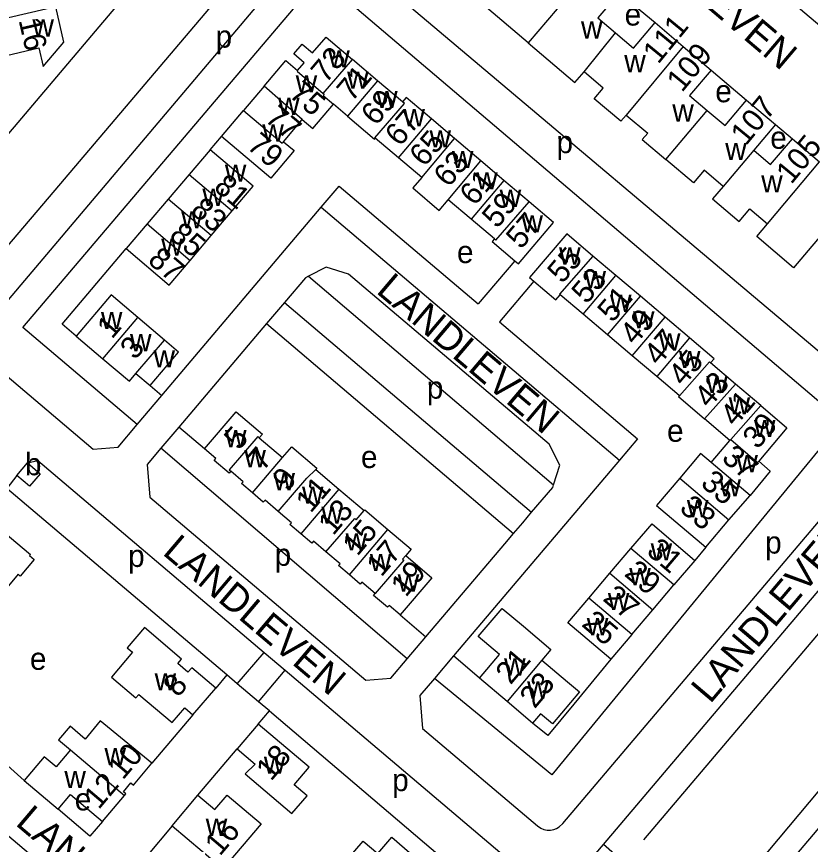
# Model space of a CAD drawing. Extents: x 155696 to 157795, y 382328 to 384028.
# Drawn here: x 156838 to 156980.5, y 382424.3 to 382573 of the extents above; entities that cross this region are included whole.
import ezdxf

# ---------------------------------------------------------------- set-up
doc = ezdxf.new("R2010")
doc.units = 0
for name, color, linetype in [('BLT_Basislijn', 7, 'Continuous'), ('BLT_Bebouwing', 7, 'Continuous'), ('BLT_Centroide', 7, 'Continuous'), ('BLT_Gemeentegrens', 7, 'Continuous'), ('BLT_Huisnummer', 7, 'Continuous'), ('BLT_Huisnummer_ tussenligend', 7, 'Continuous'), ('BLT_Onderverdeling_panden', 7, 'Continuous'), ('BLT_Straatnaam', 7, 'Continuous')]:
    doc.layers.add(name, color=color, linetype=linetype)

msp = doc.modelspace()

# ---------------------------------------------------------------- linework, layer by layer
at = {"layer": 'BLT_Basislijn'}
for p, q in [((156997.06, 382500.08), (156894.28, 382586.82)), ((156834.46, 382519.74), (156886.08, 382580.75)), ((156986.19, 382500.27), (156892.45, 382580.02)), ((156946.2, 382577.33), (156952.62, 382571.89)), ((156856.41, 382575.46), (156785.51, 382491.83)), ((156962.68, 382563.37), (156969.05, 382557.96)), ((156974.2, 382553.6), (156977.27, 382551)), ((156872.74, 382549.06), (156874.76, 382551.45)), ((156927.42, 382529.15), (156920.86, 382521.41)), ((156890.37, 382526.35), (156934.37, 382488.9)), ((156930.85, 382525.47), (156924.67, 382518.17)), ((156886.09, 382521.66), (156930.44, 382483.98)), ((157054.68, 382520.73), (156894.99, 382330.24)), ((156882.85, 382517.84), (156867.11, 382499.28)), ((156882.85, 382517.84), (156927.21, 382480.16)), ((156861.95, 382506.75), (156864.06, 382504.96)), ((156867.11, 382499.28), (156863.88, 382495.46)), ((156871.72, 382495.34), (156867.11, 382499.28)), ((156851.73, 382495.32), (156856.2, 382495.69)), ((156863.88, 382495.46), (156861.43, 382492.57)), ((156908.11, 382457.64), (156863.88, 382495.46)), ((156861.43, 382492.57), (156861.91, 382486.69)), ((156838.01, 382490.58), (156836.21, 382488.23)), ((156875.7, 382454.77), (156836.21, 382488.23)), ((156950.61, 382425.19), (157004.61, 382488.89)), ((156925.62, 382478.29), (156927.21, 382480.16)), ((156911.47, 382461.6), (156925.62, 382478.29)), ((156961.72, 382477.72), (156959.75, 382475.33)), ((156906.87, 382465.54), (156911.47, 382461.6)), ((156908.11, 382457.64), (156911.47, 382461.6)), ((156877.59, 382453.17), (156882.4, 382458.83)), ((156905.18, 382454.18), (156908.11, 382457.64)), ((156921.08, 382454.21), (156916.44, 382458.18)), ((156881.41, 382449.94), (156886.21, 382455.6)), ((156900.7, 382453.81), (156905.18, 382454.18)), ((156821.86, 382451.43), (156839.32, 382435.82)), ((156910.4, 382451.06), (156910.88, 382445.17)), ((156883.36, 382448.3), (156922.98, 382414.65)), ((156869.65, 382447.63), (156862.26, 382438.91)), ((156870.54, 382433.19), (156877.58, 382441.51)), ((156851.14, 382425.81), (156845.43, 382430.65)), ((156853.41, 382428.48), (156851.14, 382425.81))]:
    msp.add_line(p, q, dxfattribs=at)
for points in [[(156843.9, 382540.6), (156883.65, 382587.5)], [(156859.64, 382499.75), (156839.11, 382517.17), (156892.45, 382580.02)], [(156892.69, 382538.73), (156895.92, 382542.54), (156920.86, 382521.41)], [(156824.76, 382518.18), (156843.9, 382540.6)], [(156864.06, 382504.96), (156892.69, 382538.73)], [(156892.69, 382538.73), (156946.24, 382493.33)], [(156848.7, 382515.6), (156846.16, 382517.75), (156857.67, 382531.31)], [(156934.37, 382488.9), (156935.51, 382492.45), (156933.59, 382496.19), (156897.58, 382526.72), (156893.58, 382528), (156890.37, 382526.35)], [(156890.37, 382526.35), (156889.83, 382526.08), (156886.09, 382521.66)], [(156886.09, 382521.66), (156882.85, 382517.84)], [(156824.76, 382518.18), (156851.73, 382495.32)], [(156924.67, 382518.17), (156949.47, 382497.15), (156946.24, 382493.33)], [(156859.64, 382499.75), (156864.06, 382504.96)], [(156986.19, 382500.27), (156934.07, 382436.84), (156913.01, 382454.14)], [(156856.2, 382495.69), (156859.64, 382499.75)], [(156943.34, 382424.34), (157004.11, 382496.03)], [(156910.88, 382445.17), (156931.52, 382427.68), (156932.08, 382427.28), (156932.61, 382427.04), (156933.21, 382426.9), (156933.85, 382426.89), (156934.44, 382427), (156934.92, 382427.19), (156935.4, 382427.49), (156936.02, 382428.08), (156992.6, 382494.82)], [(156839.93, 382492.83), (156841.8, 382493.25), (156882.4, 382458.83)], [(156946.24, 382493.33), (156916.44, 382458.18)], [(156930.44, 382483.98), (156934.23, 382488.44), (156934.37, 382488.9)], [(156861.91, 382486.69), (156900.7, 382453.81)], [(156928.85, 382482.1), (156930.44, 382483.98)], [(156927.21, 382480.16), (156928.85, 382482.1)], [(156882.4, 382458.83), (156886.21, 382455.6)], [(156916.44, 382458.18), (156913.01, 382454.14)], [(156944.64, 382457.59), (156938.01, 382449.51)], [(156886.21, 382455.6), (156924.76, 382422.93)], [(156875.7, 382454.77), (156873.72, 382452.42)], [(156877.59, 382453.17), (156875.7, 382454.77)], [(156913.01, 382454.14), (156910.4, 382451.06)], [(156881.41, 382449.94), (156877.59, 382453.17)], [(156889.25, 382381.11), (156808.2, 382449.76)], [(156883.36, 382448.3), (156881.41, 382449.94)], [(156881.37, 382445.94), (156883.36, 382448.3)], [(156938.01, 382449.51), (156933.38, 382443.88), (156930.62, 382446.14)], [(156932.77, 382404.72), (156946.82, 382421.3), (156943.34, 382424.34)], [(156934.87, 382414.35), (156943.34, 382424.34)]]:
    msp.add_lwpolyline(points, dxfattribs=at)
at = {"layer": 'BLT_Bebouwing'}
for p, q in [((156929.84, 382568.25), (156921.59, 382575.24)), ((156842.76, 382564), (156846.49, 382568.4)), ((156902.78, 382561.45), (156898.3, 382565.25)), ((156907.26, 382557.65), (156902.78, 382561.45)), ((156882.41, 382560.47), (156878.72, 382556.13)), ((156897.39, 382555.09), (156894.88, 382557.23)), ((156885.89, 382550.51), (156889.27, 382554.5)), ((156916.59, 382551.08), (156912.44, 382554.6)), ((156906.56, 382547.63), (156902.38, 382551.16)), ((156921.31, 382547.07), (156916.59, 382551.08)), ((156910.74, 382544.11), (156906.56, 382547.63)), ((156925.46, 382543.55), (156921.31, 382547.07)), ((156868.98, 382544.63), (156865.21, 382540.19)), ((156929.99, 382539.71), (156925.46, 382543.55)), ((156865.21, 382540.19), (156861.44, 382535.75)), ((156919.61, 382536.58), (156915.45, 382540.09)), ((156872.91, 382533.65), (156876.67, 382538.09)), ((156923.77, 382533.05), (156919.61, 382536.58)), ((156869.14, 382529.21), (156872.91, 382533.65)), ((156945.56, 382526.5), (156941.46, 382529.98)), ((156949.97, 382522.76), (156945.56, 382526.5)), ((156939.67, 382519.56), (156935.57, 382523.04)), ((156954.39, 382519.02), (156949.97, 382522.76)), ((156944.09, 382515.82), (156939.67, 382519.56)), ((156864.53, 382514.88), (156859.77, 382518.92)), ((156958.8, 382515.28), (156954.39, 382519.02)), ((156948.5, 382512.08), (156944.09, 382515.82)), ((156952.91, 382508.34), (156948.5, 382512.08)), ((156967.03, 382507), (156962.55, 382510.79)), ((156956.94, 382504.92), (156952.91, 382508.34)), ((156971.57, 382503.15), (156967.03, 382507)), ((156966.04, 382496.88), (156961.51, 382500.74)), ((156881.54, 382497.37), (156885.72, 382493.83)), ((156962.69, 382492.92), (156966.04, 382496.88)), ((156965.86, 382482.61), (156969.67, 382486.99)), ((156944.5, 382473.02), (156948.28, 382477.47)), ((156940.74, 382468.58), (156944.5, 382473.02)), ((156952.21, 382466.47), (156956, 382470.93)), ((156948.44, 382462.04), (156952.21, 382466.47))]:
    msp.add_line(p, q, dxfattribs=at)
for points in [[(156946.2, 382577.33), (156942.31, 382572.75), (156945.52, 382570.03)], [(156846.49, 382568.4), (156845.03, 382574.73), (156834.68, 382572.34)], [(156977.95, 382574.98), (156982.98, 382570.71)], [(156945.52, 382570.03), (156948.74, 382567.3), (156952.62, 382571.89)], [(156952.62, 382571.89), (156957.65, 382567.63)], [(156888.44, 382563.3), (156889.61, 382564.69), (156887.75, 382566.27), (156889.23, 382568.02), (156891.09, 382566.44), (156893.53, 382569.3), (156898.3, 382565.25)], [(156836.14, 382566.01), (156841.99, 382567.36), (156842.76, 382564)], [(156929.84, 382568.25), (156938.23, 382561.15), (156939.86, 382563.05)], [(156957.65, 382567.63), (156962.68, 382563.37)], [(156882.41, 382560.47), (156886.33, 382565.09), (156888.44, 382563.3)], [(156947.42, 382555.29), (156946.46, 382554.18), (156941.67, 382558.23), (156943.29, 382560.14), (156939.86, 382563.05)], [(156962.68, 382563.37), (156958.8, 382558.79), (156961.98, 382556.09)], [(156912.44, 382554.6), (156907.92, 382558.42), (156907.26, 382557.65)], [(156889.27, 382554.5), (156891.17, 382552.85), (156894.88, 382557.23)], [(156961.98, 382556.09), (156965.17, 382553.39), (156969.05, 382557.96)], [(156969.05, 382557.96), (156974.2, 382553.6)], [(156874.76, 382551.45), (156878.72, 382556.13)], [(156897.39, 382555.09), (156902.22, 382550.99), (156902.38, 382551.16)], [(156947.42, 382555.29), (156951.28, 382552.05), (156950.31, 382550.93), (156954.56, 382547.32)], [(156974.2, 382553.6), (156970.32, 382549.01)], [(156885.89, 382550.51), (156887.8, 382548.9), (156883.61, 382543.94), (156874.76, 382551.45)], [(156970.32, 382549.01), (156973.36, 382546.44), (156977.27, 382551)], [(156977.27, 382551), (156982.12, 382546.87)], [(156872.74, 382549.06), (156868.98, 382544.63)], [(156876.67, 382538.09), (156880.44, 382542.53), (156872.74, 382549.06)], [(156964.82, 382542.47), (156961.43, 382545.4), (156959.5, 382543.13), (156954.56, 382547.32)], [(156991.99, 382545.05), (156977.45, 382527.89), (156970.86, 382533.51), (156972.79, 382535.79)], [(156910.74, 382544.11), (156909.11, 382542.21), (156913.83, 382538.17), (156915.45, 382540.09)], [(156964.82, 382542.47), (156962.91, 382540.26), (156967.7, 382536.16), (156969.64, 382538.43), (156972.79, 382535.79)], [(156934.36, 382536), (156929.99, 382539.71)], [(156927.42, 382529.15), (156928.09, 382528.59), (156934.36, 382536)], [(156861.44, 382535.75), (156857.67, 382531.31)], [(156923.77, 382533.05), (156923.38, 382532.59), (156927.42, 382529.15)], [(156936.74, 382533.98), (156930.08, 382526.13), (156930.85, 382525.47)], [(156941.46, 382529.98), (156936.74, 382533.98)], [(156857.67, 382531.31), (156865.38, 382524.78), (156869.14, 382529.21)], [(156930.85, 382525.47), (156934.8, 382522.12), (156935.57, 382523.04)], [(156859.77, 382518.92), (156854.97, 382523), (156848.7, 382515.6)], [(156848.7, 382515.6), (156853.44, 382511.53)], [(156962.55, 382510.79), (156963.21, 382511.54), (156958.8, 382515.28)], [(156861.95, 382506.75), (156867.04, 382512.75), (156864.53, 382514.88)], [(156853.44, 382511.53), (156858.23, 382507.52), (156859.41, 382508.9)], [(156859.41, 382508.9), (156861.95, 382506.75)], [(156956.94, 382504.92), (156956.8, 382504.74), (156961.51, 382500.74)], [(156971.57, 382503.15), (156976.29, 382499.15), (156971.21, 382493.15)], [(156871.72, 382495.34), (156877.4, 382502.02), (156882.1, 382498), (156881.54, 382497.37)], [(156885.72, 382493.83), (156887.38, 382495.72), (156891.91, 382491.88), (156891.71, 382491.66)], [(156876.45, 382491.34), (156876.16, 382491), (156873.43, 382493.3), (156873.73, 382493.64), (156871.72, 382495.34)], [(156962.69, 382492.92), (156960.78, 382494.53), (156957.03, 382490.11)], [(156838.01, 382490.58), (156839.93, 382492.83)], [(156839.93, 382492.83), (156842.2, 382490.9), (156840.27, 382488.65), (156838.01, 382490.58)], [(156971.21, 382493.15), (156973.29, 382491.37), (156969.67, 382486.99)], [(156880.34, 382487.47), (156878.37, 382489.13), (156878.66, 382489.47), (156876.45, 382491.34)], [(156891.71, 382491.66), (156895.84, 382488.15)], [(156957.03, 382490.11), (156952.89, 382485.22), (156961.72, 382477.72)], [(156884.94, 382484.14), (156882.58, 382486.14), (156882.27, 382485.82), (156880.34, 382487.47)], [(156895.84, 382488.15), (156900.37, 382484.3)], [(156889.02, 382480.11), (156887.06, 382481.77), (156887.35, 382482.1), (156884.94, 382484.14)], [(156900.37, 382484.3), (156900.48, 382484.43), (156904.65, 382480.89)], [(156961.72, 382477.72), (156965.86, 382482.61)], [(156904.65, 382480.89), (156908.82, 382477.36), (156907.85, 382476.22)], [(156948.28, 382477.47), (156952.07, 382481.93), (156959.75, 382475.33)], [(156830.13, 382480.33), (156833.18, 382477.74), (156835.54, 382480.52), (156840.46, 382476.39), (156840.3, 382476.2), (156841.14, 382475.5), (156838.62, 382472.53), (156838.24, 382472.85), (156834.66, 382468.63)], [(156893.52, 382476.87), (156891.28, 382478.77), (156890.98, 382478.45), (156889.02, 382480.11)], [(156897.73, 382472.73), (156895.76, 382474.4), (156896.05, 382474.73), (156893.52, 382476.87)], [(156907.85, 382476.22), (156912.53, 382472.18), (156906.87, 382465.54)], [(156959.75, 382475.33), (156956, 382470.93)], [(156902.33, 382469.39), (156899.97, 382471.4), (156899.69, 382471.07), (156897.73, 382472.73)], [(156906.87, 382465.54), (156904.87, 382467.24), (156904.59, 382466.91), (156902.04, 382469.06), (156902.33, 382469.39)], [(156944.64, 382457.59), (156936.96, 382464.13), (156940.74, 382468.58)], [(156921.08, 382454.21), (156924.68, 382458.45), (156920.87, 382461.65), (156925.18, 382466.73), (156928.98, 382463.52), (156933.92, 382459.33), (156932.3, 382457.42)], [(156873.72, 382452.42), (156869.42, 382456.07), (156868.74, 382455.28), (156866.92, 382456.82), (156867.6, 382457.62), (156860.93, 382463.28), (156857.85, 382459.64), (156858.8, 382458.85), (156855.02, 382454.37), (156859.38, 382450.65), (156859.9, 382451.27), (156865.9, 382446.21), (156868.17, 382448.88), (156869.65, 382447.63)], [(156948.44, 382462.04), (156944.64, 382457.59)], [(156932.3, 382457.42), (156936.88, 382453.54), (156939.04, 382451.72), (156934.19, 382445.98)], [(156926.03, 382450.03), (156921.08, 382454.21)], [(156869.65, 382447.63), (156873.72, 382452.42)], [(156930.62, 382446.14), (156926.03, 382450.03)], [(156934.19, 382445.98), (156932.03, 382447.81), (156930.62, 382446.14)], [(156862.26, 382438.91), (156853, 382446.52), (156850.3, 382443.24), (156847.59, 382445.56), (156845.53, 382443.14), (156847.66, 382441.33)], [(156881.37, 382445.94), (156877.58, 382441.51)], [(156877.58, 382441.51), (156880.79, 382438.76), (156879.02, 382437.02), (156887.41, 382429.91), (156890.12, 382433.08), (156887.84, 382435.02), (156890.52, 382438.19), (156881.37, 382445.94)], [(156847.66, 382441.33), (156845.09, 382438.29), (156842.95, 382440.09), (156839.32, 382435.82)], [(156857.33, 382433.1), (156857.6, 382433.42), (156857.15, 382433.8), (156858.49, 382435.38), (156858.94, 382435), (156862.26, 382438.91)], [(156839.32, 382435.82), (156845.43, 382430.65)], [(156845.43, 382430.65), (156847.68, 382433.31), (156853.41, 382428.48)], [(156853.41, 382428.48), (156857.33, 382433.1)], [(156865.92, 382427.7), (156870.54, 382433.19)], [(156870.54, 382433.19), (156873.6, 382430.62), (156875.81, 382433.21), (156881.89, 382428.03), (156875.07, 382419.99)], [(156865.92, 382427.7), (156861.29, 382422.2)], [(156896.87, 382421.03), (156900.19, 382424.92), (156902.81, 382422.69), (156905.32, 382425.64), (156909.9, 382421.7), (156908.87, 382420.45), (156910.19, 382419.32), (156910.71, 382419.94), (156917.01, 382414.59), (156911.77, 382408.44), (156907.58, 382411.98)]]:
    msp.add_lwpolyline(points, dxfattribs=at)
at = {"layer": 'BLT_Gemeentegrens'}
msp.add_lwpolyline([(157057.24, 382509.64), (157054.13, 382512.28), (156977.61, 382422.16), (156897.72, 382327.92), (156894.99, 382330.24)], dxfattribs=at)
at = {"layer": 'BLT_Onderverdeling_panden'}
for p, q in [((156941.17, 382581.6), (156929.84, 382568.25)), ((156939.86, 382563.05), (156945.52, 382570.03)), ((156957.65, 382567.63), (156947.42, 382555.29)), ((156893.04, 382559.17), (156898.3, 382565.25)), ((156902.78, 382561.45), (156897.39, 382555.09)), ((156889.27, 382554.5), (156882.41, 382560.47)), ((156954.56, 382547.32), (156961.98, 382556.09)), ((156906.56, 382547.63), (156912.44, 382554.6)), ((156910.74, 382544.11), (156916.59, 382551.08)), ((156970.32, 382549.01), (156964.82, 382542.47)), ((156915.45, 382540.09), (156921.31, 382547.07)), ((156972.79, 382535.79), (156982.12, 382546.87)), ((156868.98, 382544.63), (156876.67, 382538.09)), ((156925.46, 382543.55), (156919.61, 382536.58)), ((156872.91, 382533.65), (156865.21, 382540.19)), ((156861.44, 382535.75), (156869.14, 382529.21)), ((156939.67, 382519.56), (156945.56, 382526.5)), ((156944.09, 382515.82), (156949.97, 382522.76)), ((156853.44, 382511.53), (156859.77, 382518.92)), ((156948.5, 382512.08), (156954.39, 382519.02)), ((156958.8, 382515.28), (156952.91, 382508.34)), ((156859.41, 382508.9), (156864.53, 382514.88)), ((156961.51, 382500.74), (156967.03, 382507)), ((156971.57, 382503.15), (156966.18, 382497.03)), ((156966.18, 382497.03), (156966.04, 382496.88)), ((156880.34, 382487.47), (156885.72, 382493.83)), ((156969.67, 382486.99), (156962.69, 382492.92)), ((156895.84, 382488.15), (156889.02, 382480.11)), ((156897.73, 382472.73), (156904.65, 382480.89)), ((156956, 382470.93), (156948.28, 382477.47)), ((156944.5, 382473.02), (156952.21, 382466.47)), ((156948.44, 382462.04), (156940.74, 382468.58)), ((156932.3, 382457.42), (156926.03, 382450.03)), ((156847.66, 382441.33), (156857.33, 382433.1)), ((156865.92, 382427.7), (156875.07, 382419.99))]:
    msp.add_line(p, q, dxfattribs=at)
for points in [[(156888.44, 382563.3), (156888.34, 382563.19), (156893.04, 382559.17)], [(156893.04, 382559.17), (156893.22, 382559.02), (156893.03, 382558.8), (156894.88, 382557.23)], [(156902.38, 382551.16), (156902.32, 382551.22), (156907.62, 382557.34), (156907.26, 382557.65)], [(156878.72, 382556.13), (156885.66, 382550.24), (156885.89, 382550.51)], [(156923.77, 382533.05), (156924.04, 382532.82), (156929.99, 382539.71)], [(156941.46, 382529.98), (156935.44, 382523.15), (156935.57, 382523.04)], [(156956.94, 382504.92), (156956.99, 382504.88), (156962.35, 382510.97), (156962.55, 382510.79)], [(156881.54, 382497.37), (156881.3, 382497.57), (156876.16, 382491.6), (156876.45, 382491.34)], [(156966.18, 382497.03), (156971.01, 382492.93), (156971.21, 382493.15)], [(156884.94, 382484.14), (156890.11, 382490.12), (156891.71, 382491.66)], [(156957.03, 382490.11), (156965.86, 382482.61)], [(156893.52, 382476.87), (156898.69, 382482.85), (156898.95, 382482.64), (156900.37, 382484.3)], [(156907.85, 382476.22), (156907.29, 382475.56), (156907.5, 382475.38), (156902.33, 382469.39)]]:
    msp.add_lwpolyline(points, dxfattribs=at)

# ---------------------------------------------------------------- texts
at = {"layer": 'BLT_Centroide'}
for s, p in [('e', (156947.14, 382571.36)), ('w', (156840.82, 382569.38)), ('w', (156939.31, 382569.03)), ('p', (156873.7, 382567.4)), ('w', (156893.94, 382563.86)), ('w', (156947.07, 382562.99)), ('w', (156897.31, 382560.04)), ('w', (156888.09, 382559.36)), ('w', (156902.53, 382556.56)), ('e', (156963.41, 382557.59)), ('w', (156884.93, 382555.33)), ('w', (156955.7, 382554.13)), ('w', (156907.43, 382553.29)), ('w', (156882.1, 382550.54)), ('w', (156912.11, 382549.48)), ('e', (156973.28, 382549.24)), ('p', (156934.91, 382548.45)), ('w', (156965.19, 382547.23)), ('w', (156916.14, 382545.77)), ('w', (156875.37, 382543.34)), ('w', (156920.49, 382541.96)), ('w', (156971.66, 382541.4)), ('w', (156871.34, 382538.99)), ('w', (156924.71, 382538.8)), ('w', (156867.53, 382534.96)), ('w', (156928.62, 382534.23)), ('w', (156863.94, 382530.05)), ('e', (156917.04, 382528.72)), ('w', (156935.37, 382528.45)), ('w', (156939.94, 382524.2)), ('w', (156944.51, 382519.96)), ('w', (156853.12, 382516.89)), ('w', (156948.65, 382517.01)), ('w', (156858.34, 382512.9)), ('w', (156953.3, 382513.01)), ('w', (156862.56, 382509.98)), ('w', (156956.89, 382509.85)), ('w', (156961.79, 382505.39)), ('p', (156911.63, 382504.37)), ('w', (156965.82, 382501.57)), ('w', (156970.36, 382497.49)), ('w', (156875.39, 382495.66)), ('e', (156954.75, 382496.63)), ('b', (156839.47, 382490.62)), ('w', (156878.87, 382492.07)), ('e', (156899.8, 382491.92)), ('w', (156967.2, 382491.17)), ('w', (156884.09, 382487.93)), ('w', (156964.16, 382486.81)), ('w', (156889.21, 382485.53)), ('w', (156958.32, 382483.08)), ('w', (156892.69, 382481.94)), ('w', (156897.05, 382477.14)), ('p', (156972.36, 382476.56)), ('w', (156951.81, 382475.35)), ('p', (156858, 382474.16)), ('p', (156884.3, 382474.36)), ('w', (156901.4, 382473.44)), ('w', (156947.97, 382470.88)), ('w', (156906.4, 382469.74)), ('w', (156944.13, 382466.42)), ('w', (156940.35, 382461.9)), ('e', (156840.37, 382455.69)), ('w', (156925.5, 382454.67)), ('w', (156862.76, 382452.01)), ('w', (156929.64, 382450.53)), ('w', (156853.76, 382438.57)), ('w', (156882.37, 382437.04)), ('w', (156846.56, 382434.45)), ('p', (156905.41, 382433.91)), ('e', (156848.42, 382430.45)), ('w', (156871.94, 382425.88))]:
    msp.add_text(s, height=4, dxfattribs=at).set_placement(p)
at = {"layer": 'BLT_Huisnummer'}
for s, rotation, p in [('16', 283.0092, (156838.32, 382572.32)), ('111', 50.5751, (156953.17, 382564.3)), ('71', 49.7095, (156898.17, 382557.52)), ('75', 319.7095, (156886.7, 382558.74)), ('107', 50.5751, (156968.92, 382549.67)), ('67', 49.7095, (156906.81, 382549.48)), ('79', 319.7095, (156879.13, 382549.46)), ('63', 49.7095, (156915.54, 382542.15)), ('81', 319.7095, (156873.17, 382542.03)), ('59', 49.7095, (156924.23, 382534.77)), ('57', 49.7095, (156928.54, 382531.04)), ('87', 319.7095, (156861.33, 382528.91)), ('55', 49.7095, (156935.95, 382524.87)), ('51', 49.7095, (156944.96, 382517.87)), ('1', 49.7095, (156855.1, 382514.94)), ('47', 49.7095, (156953.26, 382510.12)), ('3', 49.7095, (156859.25, 382511.18)), ('43', 49.7095, (156962.33, 382502.5)), ('39', 49.7095, (156971.02, 382495.13)), ('5', 49.7095, (156877.91, 382494.96)), ('35', 319.7095, (156960.59, 382488.87)), ('11', 49.7095, (156890.78, 382483.69)), ('33', 319.7095, (156956.79, 382484.38)), ('15', 49.7095, (156899.16, 382475.95)), ('31', 319.7095, (156950.88, 382476.65)), ('19', 49.7095, (156907.85, 382468.58)), ('25', 319.7095, (156939.24, 382463.68)), ('21', 49.7095, (156926.66, 382452.88)), ('8', 49.6852, (156866.98, 382450.6)), ('23', 49.7095, (156930.99, 382448.58)), ('10', 49.6852, (156857.06, 382435.79)), ('18', 49.6852, (156883.67, 382435.57)), ('12', 49.6852, (156852.72, 382430.47)), ('16', 49.6852, (156874.47, 382422.11))]:
    msp.add_text(s, height=4, rotation=rotation, dxfattribs=at).set_placement(p)
at = {"layer": 'BLT_Huisnummer_ tussenligend'}
for s, rotation, p in [('73', 49.7095, (156893.51, 382560.84)), ('109', 50.5751, (156957.43, 382559.22)), ('69', 49.7095, (156902.5, 382553.21)), ('77', 319.7095, (156882.36, 382554.36)), ('65', 49.7095, (156911.19, 382545.83)), ('105', 50.5751, (156977.07, 382542.72)), ('61', 49.7095, (156920.2, 382538.83)), ('83', 319.7095, (156869, 382537.85)), ('85', 319.7095, (156865.18, 382533.36)), ('53', 49.7095, (156940.3, 382521.19)), ('49', 49.7095, (156948.99, 382513.81)), ('45', 49.7095, (156957.68, 382506.44)), ('41', 49.7095, (156966.99, 382499.18)), ('7', 49.7095, (156882.22, 382491.23)), ('37', 319.7095, (156964.36, 382493.4)), ('9', 49.7095, (156886.6, 382487.59)), ('13', 49.7095, (156894.81, 382479.64)), ('17', 49.7095, (156903.47, 382472.22)), ('29', 319.7095, (156946.9, 382472.71)), ('27', 319.7095, (156943.05, 382468.26))]:
    msp.add_text(s, height=4, rotation=rotation, dxfattribs=at).set_placement(p)
at = {"layer": 'BLT_Straatnaam'}
for rotation, p in [(319.7122, (156944.99, 382588.84)), (319.7122, (156902.36, 382523.48)), (49.7122, (156962.51, 382449.46)), (319.7122, (156864, 382476.53)), (319.7122, (156837.6, 382427.94))]:
    msp.add_text('LANDLEVEN', height=5, rotation=rotation, dxfattribs=at).set_placement(p)

doc.saveas('drawing.dxf')
